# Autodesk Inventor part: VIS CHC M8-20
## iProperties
Created: 2004-11
Part Number: VIS CHC M8-20
Document SubType Name: Modeling
Designer: Bruno
Manufacturer: Standard
Standards Organization: Custom
Author: Bruno
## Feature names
1. Base1
